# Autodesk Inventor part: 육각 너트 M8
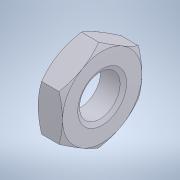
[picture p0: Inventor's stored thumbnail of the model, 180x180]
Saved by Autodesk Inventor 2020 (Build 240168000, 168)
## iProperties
Created: 2024-04
Part Number: 육각 너트 M8
Material: 강철, 연강
Description: 6각 너트 및 6각 가는 너트 - 이중 모따기
Document SubType Name: Modeling
Designer: oem
Density: 7.86 g/cm^3
Appearance: 기본값
Author: jhkim
Sending System: Autodesk Inventor 2025
Preprocessor: ST-DEVELOPER v20
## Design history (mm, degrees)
feature "Solid1"
node "솔리드1"
